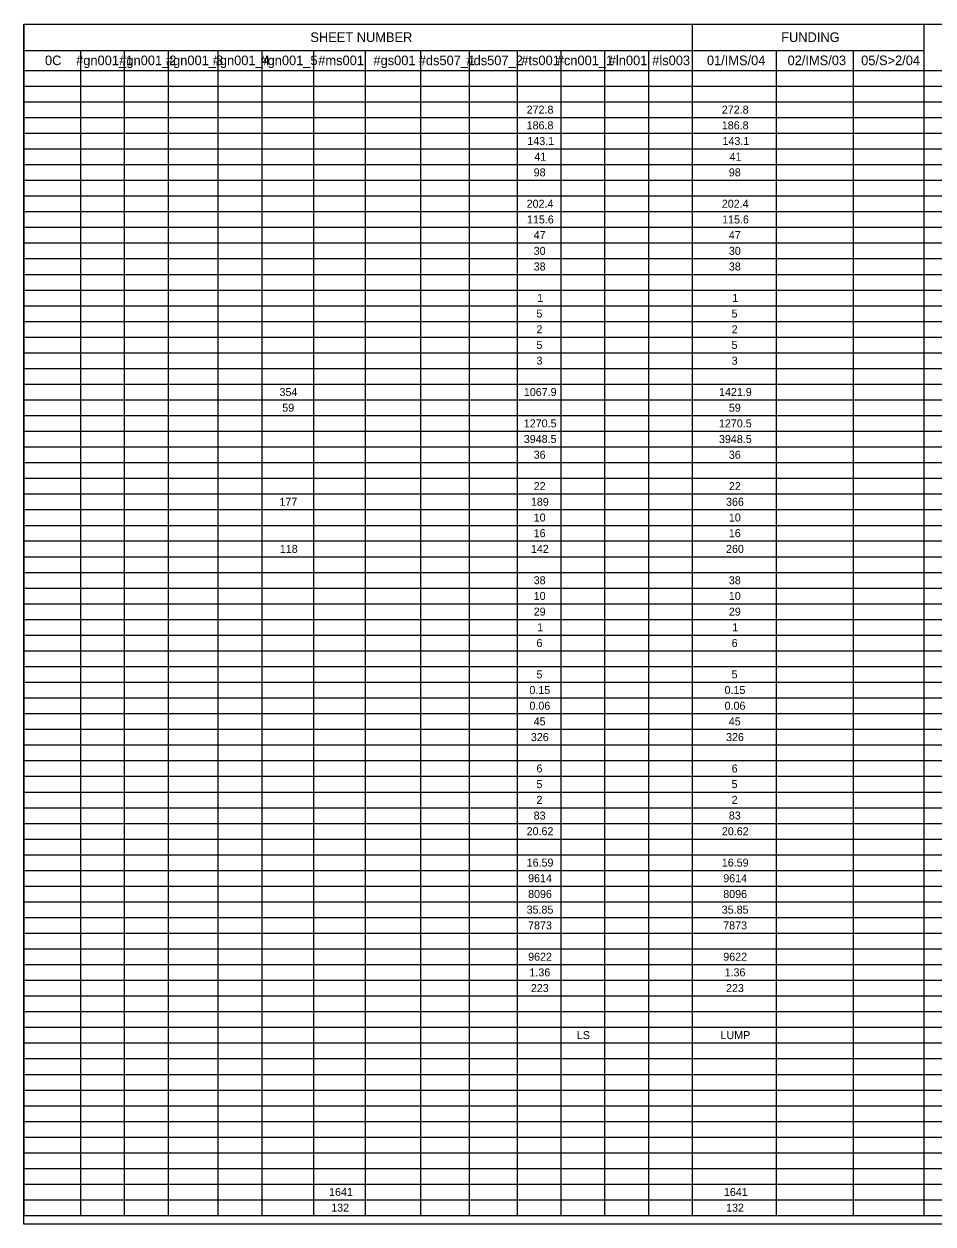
# Model space of a CAD drawing. Extents: x -542 to 295, y -281 to 32.
# Drawn here: x -416.36 to -400.45, y -130.59 to -109.59 of the extents above; entities that cross this region are included whole.
import ezdxf

# ---------------------------------------------------------------- set-up
doc = ezdxf.new("R2010")
doc.units = 0
for name, color, linetype in [('SC_Scratch1', 7, 'Continuous'), ('SH_Data', 7, 'Continuous'), ('SH_Text', 7, 'Continuous')]:
    doc.layers.add(name, color=color, linetype=linetype)

msp = doc.modelspace()

# ---------------------------------------------------------------- linework, layer by layer
at = {"layer": 'SC_Scratch1'}
msp.add_lwpolyline([(-416.359, -109.593), (-385.859, -109.593), (-385.859, -130.593), (-416.359, -130.593)], close=True, dxfattribs=at)
at = {"layer": 'SH_Data'}
for p, q in [((-416.359, -109.593), (-385.859, -109.593)), ((-416.359, -109.593), (-416.359, -130.444)), ((-404.663, -109.593), (-404.663, -130.444)), ((-400.608, -109.593), (-400.608, -130.444)), ((-416.359, -110.054), (-400.608, -110.054)), ((-415.369, -110.054), (-415.369, -130.444)), ((-414.603, -110.054), (-414.603, -130.444)), ((-413.836, -110.054), (-413.836, -130.444)), ((-412.964, -110.054), (-412.964, -130.444)), ((-412.198, -110.054), (-412.198, -130.444)), ((-411.293, -110.054), (-411.293, -130.444)), ((-410.388, -110.054), (-410.388, -130.444)), ((-409.42, -110.054), (-409.42, -130.444)), ((-408.569, -110.054), (-408.569, -130.444)), ((-407.728, -110.054), (-407.728, -130.444)), ((-406.962, -110.054), (-406.962, -130.444)), ((-406.195, -110.054), (-406.195, -130.444)), ((-405.429, -110.054), (-405.429, -130.444)), ((-403.194, -110.054), (-403.194, -130.444)), ((-401.843, -110.054), (-401.843, -130.444)), ((-416.359, -110.405), (-385.859, -110.405)), ((-416.359, -110.68), (-385.859, -110.68)), ((-416.359, -110.68), (-385.859, -110.68)), ((-416.359, -110.954), (-385.859, -110.954)), ((-416.359, -111.229), (-385.859, -111.229)), ((-416.359, -111.503), (-385.859, -111.503)), ((-416.359, -111.778), (-385.859, -111.778)), ((-416.359, -112.052), (-385.859, -112.052)), ((-416.359, -112.327), (-385.859, -112.327)), ((-416.359, -112.601), (-385.859, -112.601)), ((-416.359, -112.876), (-385.859, -112.876)), ((-416.359, -113.15), (-385.859, -113.15)), ((-416.359, -113.425), (-385.859, -113.425)), ((-416.359, -113.699), (-385.859, -113.699)), ((-416.359, -113.974), (-385.859, -113.974)), ((-416.359, -114.248), (-385.859, -114.248)), ((-416.359, -114.523), (-385.859, -114.523)), ((-416.359, -114.797), (-385.859, -114.797)), ((-416.359, -115.072), (-385.859, -115.072)), ((-416.359, -115.346), (-385.859, -115.346)), ((-416.359, -115.621), (-385.859, -115.621)), ((-416.359, -115.895), (-385.859, -115.895)), ((-416.359, -116.17), (-385.859, -116.17)), ((-416.359, -116.444), (-385.859, -116.444)), ((-416.359, -116.719), (-385.859, -116.719)), ((-416.359, -116.993), (-385.859, -116.993)), ((-416.359, -117.268), (-385.859, -117.268)), ((-416.359, -117.542), (-385.859, -117.542)), ((-416.359, -117.817), (-385.859, -117.817)), ((-416.359, -118.091), (-385.859, -118.091)), ((-416.359, -118.366), (-385.859, -118.366)), ((-416.359, -118.64), (-385.859, -118.64)), ((-416.359, -118.915), (-385.859, -118.915)), ((-416.359, -119.189), (-385.859, -119.189)), ((-416.359, -119.464), (-385.859, -119.464)), ((-416.359, -119.738), (-385.859, -119.738)), ((-416.359, -120.013), (-385.859, -120.013)), ((-416.359, -120.287), (-385.859, -120.287)), ((-416.359, -120.562), (-385.859, -120.562)), ((-416.359, -120.836), (-385.859, -120.836)), ((-416.359, -121.111), (-385.859, -121.111)), ((-416.359, -121.385), (-385.859, -121.385)), ((-416.359, -121.66), (-385.859, -121.66)), ((-416.359, -121.935), (-385.859, -121.935)), ((-416.359, -122.209), (-385.859, -122.209)), ((-416.359, -122.484), (-385.859, -122.484)), ((-416.359, -122.758), (-385.859, -122.758)), ((-416.359, -123.033), (-385.859, -123.033)), ((-416.359, -123.307), (-385.859, -123.307)), ((-416.359, -123.582), (-385.859, -123.582)), ((-416.359, -123.856), (-385.859, -123.856)), ((-416.359, -124.131), (-385.859, -124.131)), ((-416.359, -124.405), (-385.859, -124.405)), ((-416.359, -124.68), (-385.859, -124.68)), ((-416.359, -124.954), (-385.859, -124.954)), ((-416.359, -125.229), (-385.859, -125.229)), ((-416.359, -125.229), (-385.859, -125.229)), ((-416.359, -125.503), (-385.859, -125.503)), ((-416.359, -125.778), (-385.859, -125.778)), ((-416.359, -126.052), (-385.859, -126.052)), ((-416.359, -126.327), (-385.859, -126.327)), ((-416.359, -126.601), (-385.859, -126.601)), ((-416.359, -126.876), (-385.859, -126.876)), ((-416.359, -127.15), (-385.859, -127.15)), ((-416.359, -127.425), (-385.859, -127.425)), ((-416.359, -127.699), (-385.859, -127.699)), ((-416.359, -127.974), (-385.859, -127.974)), ((-416.359, -128.248), (-385.859, -128.248)), ((-416.359, -128.523), (-385.859, -128.523)), ((-416.359, -128.797), (-385.859, -128.797)), ((-416.359, -129.072), (-385.859, -129.072)), ((-416.359, -129.346), (-385.859, -129.346)), ((-416.359, -129.346), (-385.859, -129.346)), ((-416.359, -129.621), (-385.859, -129.621)), ((-416.359, -129.895), (-385.859, -129.895)), ((-416.359, -130.17), (-385.859, -130.17)), ((-416.359, -130.444), (-385.859, -130.444)), ((-416.357, -130.444), (-385.857, -130.444))]:
    msp.add_line(p, q, dxfattribs=at)

# ---------------------------------------------------------------- texts
at = {"layer": 'SH_Text'}
for s, height, p in [('SHEET NUMBER', 0.168, (-411.346, -109.907)), ('FUNDING', 0.168, (-403.105, -109.907)), ('0C', 0.168, (-415.991, -110.313)), ('#gn001_1', 0.168, (-415.446, -110.313)), ('#gn001_2', 0.168, (-414.691, -110.313)), ('#gn001_3', 0.168, (-413.873, -110.313)), ('#gn001_4', 0.168, (-413.055, -110.313)), ('#gn001_5', 0.168, (-412.219, -110.313)), ('#ms001', 0.168, (-411.207, -110.313)), ('#gs001', 0.168, (-410.242, -110.313)), ('#ds507_1', 0.168, (-409.449, -110.313)), ('#ds507_2', 0.168, (-408.614, -110.313)), ('#ts001', 0.168, (-407.654, -110.313)), ('#cn001_1', 0.168, (-407.033, -110.313)), ('#ln001', 0.168, (-406.122, -110.313)), ('#ls003', 0.168, (-405.362, -110.313)), ('01/IMS/04', 0.168, (-404.405, -110.313)), ('02/IMS/03', 0.168, (-402.993, -110.313)), ('05/S>2/04', 0.168, (-401.705, -110.313)), ('272.8', 0.14, (-407.56, -111.161)), ('272.8', 0.14, (-404.144, -111.161)), ('186.8', 0.14, (-407.56, -111.436)), ('186.8', 0.14, (-404.144, -111.436)), ('143.1', 0.14, (-407.548, -111.71)), ('143.1', 0.14, (-404.132, -111.71)), ('41', 0.14, (-407.425, -111.985)), ('41', 0.14, (-404.009, -111.985)), ('98', 0.14, (-407.437, -112.259)), ('98', 0.14, (-404.021, -112.259)), ('202.4', 0.14, (-407.56, -112.808)), ('202.4', 0.14, (-404.144, -112.808)), ('115.6', 0.14, (-407.554, -113.083)), ('115.6', 0.14, (-404.138, -113.083)), ('47', 0.14, (-407.437, -113.357)), ('47', 0.14, (-404.021, -113.357)), ('30', 0.14, (-407.437, -113.632)), ('30', 0.14, (-404.021, -113.632)), ('38', 0.14, (-407.437, -113.906)), ('38', 0.14, (-404.021, -113.906)), ('1', 0.14, (-407.376, -114.455)), ('1', 0.14, (-403.96, -114.455)), ('5', 0.14, (-407.389, -114.73)), ('5', 0.14, (-403.973, -114.73)), ('2', 0.14, (-407.388, -115.005)), ('2', 0.14, (-403.972, -115.005)), ('5', 0.14, (-407.389, -115.279)), ('5', 0.14, (-403.973, -115.279)), ('3', 0.14, (-407.388, -115.554)), ('3', 0.14, (-403.972, -115.554)), ('354', 0.14, (-411.886, -116.103)), ('1067.9', 0.14, (-407.609, -116.103)), ('1421.9', 0.14, (-404.193, -116.103)), ('59', 0.14, (-411.838, -116.377)), ('59', 0.14, (-404.021, -116.377)), ('1270.5', 0.14, (-407.61, -116.652)), ('1270.5', 0.14, (-404.194, -116.652)), ('3948.5', 0.14, (-407.61, -116.926)), ('3948.5', 0.14, (-404.194, -116.926)), ('36', 0.14, (-407.437, -117.201)), ('36', 0.14, (-404.021, -117.201)), ('22', 0.14, (-407.437, -117.75)), ('22', 0.14, (-404.02, -117.75)), ('177', 0.14, (-411.887, -118.024)), ('189', 0.14, (-407.486, -118.024)), ('366', 0.14, (-404.07, -118.024)), ('10', 0.14, (-407.437, -118.299)), ('10', 0.14, (-404.021, -118.299)), ('16', 0.14, (-407.437, -118.573)), ('16', 0.14, (-404.021, -118.573)), ('118', 0.14, (-411.88, -118.848)), ('142', 0.14, (-407.485, -118.848)), ('260', 0.14, (-404.07, -118.848)), ('38', 0.14, (-407.437, -119.397)), ('38', 0.14, (-404.021, -119.397)), ('10', 0.14, (-407.437, -119.671)), ('10', 0.14, (-404.021, -119.671)), ('29', 0.14, (-407.437, -119.946)), ('29', 0.14, (-404.021, -119.946)), ('1', 0.14, (-407.376, -120.22)), ('1', 0.14, (-403.96, -120.22)), ('6', 0.14, (-407.388, -120.495)), ('6', 0.14, (-403.972, -120.495)), ('5', 0.14, (-407.389, -121.044)), ('5', 0.14, (-403.973, -121.044)), ('0.15', 0.14, (-407.512, -121.318)), ('0.15', 0.14, (-404.096, -121.318)), ('0.06', 0.14, (-407.511, -121.593)), ('0.06', 0.14, (-404.095, -121.593)), ('45', 0.14, (-407.438, -121.867)), ('45', 0.14, (-404.022, -121.867)), ('326', 0.14, (-407.486, -122.142)), ('326', 0.14, (-404.07, -122.142)), ('6', 0.14, (-407.388, -122.691)), ('6', 0.14, (-403.972, -122.691)), ('5', 0.14, (-407.389, -122.965)), ('5', 0.14, (-403.973, -122.965)), ('2', 0.14, (-407.388, -123.24)), ('2', 0.14, (-403.972, -123.24)), ('83', 0.14, (-407.437, -123.514)), ('83', 0.14, (-404.021, -123.514)), ('20.62', 0.14, (-407.56, -123.789)), ('20.62', 0.14, (-404.143, -123.789)), ('16.59', 0.14, (-407.56, -124.338)), ('16.59', 0.14, (-404.144, -124.338)), ('9614', 0.14, (-407.535, -124.612)), ('9614', 0.14, (-404.119, -124.612)), ('8096', 0.14, (-407.535, -124.887)), ('8096', 0.14, (-404.119, -124.887)), ('35.85', 0.14, (-407.561, -125.161)), ('35.85', 0.14, (-404.145, -125.161)), ('7873', 0.14, (-407.535, -125.436)), ('7873', 0.14, (-404.119, -125.436)), ('9622', 0.14, (-407.534, -125.985)), ('9622', 0.14, (-404.118, -125.985)), ('1.36', 0.14, (-407.511, -126.259)), ('1.36', 0.14, (-404.095, -126.259)), ('223', 0.14, (-407.486, -126.534)), ('223', 0.14, (-404.07, -126.534)), ('LS', 0.14, (-406.68, -127.357)), ('LUMP', 0.14, (-404.166, -127.357)), ('1641', 0.14, (-411.019, -130.103)), ('1641', 0.14, (-404.107, -130.103)), ('132', 0.14, (-410.981, -130.377)), ('132', 0.14, (-404.069, -130.377))]:
    msp.add_text(s, height=height, dxfattribs=at).set_placement(p)

doc.saveas('drawing.dxf')
